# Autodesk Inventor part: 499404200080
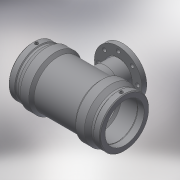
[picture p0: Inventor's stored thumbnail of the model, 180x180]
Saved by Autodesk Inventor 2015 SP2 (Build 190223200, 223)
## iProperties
Created: 2017-06
Part Number: 499404200080
Material: Generic
Description: PLASSON FLANGED TEE 200x80x200
Document SubType Name: Modeling
Designer: KIM
Mass: 57.3761 g
Surface Area: 241.06 cm^2
Volume: 57.3761 cm^3
Density: 1 g/cm^3
Appearance: Default
Author: KIM
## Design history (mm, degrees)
derived "499404.ipt"
feature "Solid1::499404.ipt"
tag "TaggingFeature1"
body "Solid1"
other parameters: "d13" = 451, "d14" = 17.6296, "d19" = 3.52592, "d20" = 168 deg, "d22" = 242.73, "d23" = 261, "d24" = 235.4481, "d25" = 135 deg, "d26" = 315.7, "d27" = 135 deg, "d29" = 125, "d35" = 15, "d39" = 5 deg, "d45" = 4, "d46" = 14, "d47" = 0, "d55" = 234.9, "d56" = 261, "d57" = 157.85, "d58" = 135 deg, "d59" = 114, "d60" = 114, "d61" = 135 deg, "d72" = 205.205, "d73" = 102.6025, "d87" = 138, "d89" = 96, "d91" = 15 deg, "d92" = 104, "d95" = 4.14, "d97" = 18, "d100" = 0, "d102" = 360 deg, "d105" = 0, "d107" = 0, "d108" = 3, "d109" = 0, "d110" = 34.2, "d111" = 11.4, "L_" = 451, "L_1" = 114, "D_" = 261, "A_" = 125, "d_2" = 12, "d_1" = 138, "s_" = 18
